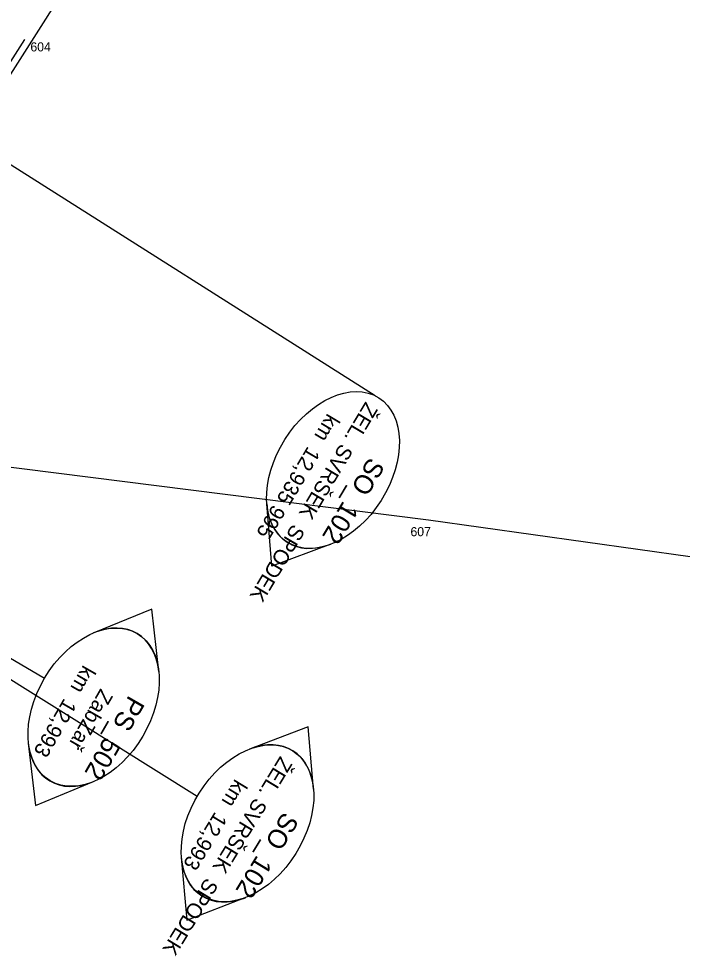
# Model space of a CAD drawing. Extents: x -743546 to -74, y -1128126 to -103.
# Drawn here: x -743132.9 to -743045.6, y -1127159.4 to -1127036 of the extents above; entities that cross this region are included whole.
import ezdxf

# ---------------------------------------------------------------- set-up
doc = ezdxf.new("R2010")
doc.units = 0
for name, color, linetype in [('_Násyp', 7, 'Continuous'), ('_TRASA_vedení kabelu_CEZ', 7, 'Continuous'), ('bublina_fialová_čára_tenká', 7, 'Continuous'), ('bublina_růžová_230_čára_tučná', 7, 'Continuous'), ('křížky', 7, 'Continuous'), ('Vrstva 53', 7, 'Continuous'), ('Vrstva 60', 7, 'Continuous')]:
    doc.layers.add(name, color=color, linetype=linetype)

# ---------------------------------------------------------------- blocks, each defined once
blk = doc.blocks.new('POINT_DISPLAY')
blk.add_line((0, 0), (0, 0))

msp = doc.modelspace()

# ---------------------------------------------------------------- linework, layer by layer
at = {"layer": '_TRASA_vedení kabelu_CEZ'}
for points in [[(-743153.07, -1127080.41), (-743148.26, -1127068.65), (-743137.26, -1127046.76), (-743132.07, -1127038.68)], [(-743154.26, -1127082.61), (-743159.25, -1127091.79), (-743078.98, -1127101.9), (-743017.04, -1127110.61), (-742993.93, -1127114.82), (-742964.82, -1127120.76), (-742937.74, -1127126.54), (-742940.65, -1127140.7), (-742943, -1127146.4)]]:
    msp.add_lwpolyline(points, dxfattribs=at)
at = {"layer": 'bublina_fialová_čára_tenká'}
for p, q in [((-743086, -1127085.59), (-743143.43, -1127049.19)), ((-743129.51, -1127122.8), (-743175.48, -1127095.85)), ((-743109.42, -1127138.31), (-743174.12, -1127097.81))]:
    msp.add_line(p, q, dxfattribs=at)
at = {"layer": 'bublina_růžová_230_čára_tučná'}
for p, q in [((-743099.58, -1127108.03), (-743100.27, -1127099.8)), ((-743099.58, -1127108.03), (-743100.27, -1127099.8)), ((-743091.85, -1127105.13), (-743099.58, -1127108.03)), ((-743091.85, -1127105.13), (-743099.58, -1127108.03)), ((-743115.4, -1127113.65), (-743123.03, -1127116.79)), ((-743115.4, -1127113.65), (-743123.03, -1127116.79)), ((-743114.46, -1127121.85), (-743115.4, -1127113.65)), ((-743114.46, -1127121.85), (-743115.4, -1127113.65)), ((-743094.84, -1127129.14), (-743102.55, -1127132.08)), ((-743094.84, -1127129.14), (-743102.55, -1127132.08)), ((-743094.11, -1127137.36), (-743094.84, -1127129.14)), ((-743094.11, -1127137.36), (-743094.84, -1127129.14)), ((-743131.63, -1127131.3), (-743130.69, -1127139.51)), ((-743131.63, -1127131.3), (-743130.69, -1127139.51)), ((-743130.69, -1127139.51), (-743123.06, -1127136.36)), ((-743130.69, -1127139.51), (-743123.06, -1127136.36)), ((-743111.53, -1127146.36), (-743110.8, -1127154.58)), ((-743111.53, -1127146.36), (-743110.8, -1127154.58)), ((-743110.8, -1127154.58), (-743103.09, -1127151.64)), ((-743110.8, -1127154.58), (-743103.09, -1127151.64))]:
    msp.add_line(p, q, dxfattribs=at)
for centre, major_axis in [((-743091.56, -1127095.35), (6.01, 9.51)), ((-743123.03, -1127126.57), (-5.72, -9.69)), ((-743102.8, -1127141.85), (-5.97, -9.53))]:
    msp.add_ellipse(centre, major_axis=major_axis, ratio=0.666667, dxfattribs=at)
for centre, major_axis in [((-743091.56, -1127095.35), (-6.02, -9.51)), ((-743123.03, -1127126.57), (5.72, 9.69)), ((-743102.8, -1127141.85), (5.97, 9.54)), ((-743123.07, -1127126.59), (-5.72, -9.69)), ((-743102.84, -1127141.87), (-5.97, -9.54))]:
    msp.add_ellipse(centre, major_axis=major_axis, ratio=0.666473, start_param=5.557317, end_param=7.009053, dxfattribs=at)
at = {"layer": 'Vrstva 53'}
msp.add_lwpolyline([(-743032.8, -1126884.17), (-743063.8, -1126932.98), (-743082.27, -1126962.07), (-743093.1, -1126978.92), (-743136.47, -1127047.12), (-743147.78, -1127068.8), (-743159.64, -1127094.74), (-743160.17, -1127095.91), (-743166.78, -1127095.57), (-743176.42, -1127093.47), (-743180.17, -1127093.19), (-743180.08, -1127092.14), (-743178.51, -1127091.81), (-743175.35, -1127091.16), (-743150.08, -1127051.72), (-743124.8, -1127012.28), (-743108.67, -1126985.4), (-743080.97, -1126930.41), (-743079.79, -1126928.05), (-743048.51, -1126865.51)], dxfattribs=at)
at = {"layer": 'Vrstva 60'}
for p, q in [((-743132.07, -1127038.68), (-743132.07, -1127038.68)), ((-743078.98, -1127101.9), (-743078.98, -1127101.9))]:
    msp.add_line(p, q, dxfattribs=at)

# ---------------------------------------------------------------- block references
at = {"layer": 'křížky', "xscale": 10, "yscale": 10, "rotation": 61.14491455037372}
for p in [(-743132.07, -1127038.68), (-743078.98, -1127101.9)]:
    msp.add_blockref('POINT_DISPLAY', p, dxfattribs=at)

# ---------------------------------------------------------------- texts
at = {"layer": '_Násyp'}
for s, height, rotation, p in [('ŽEL. SVRŠEK  SPODEK', 2, 239.1744, (-743087.27, -1127086.27)), ('km  12,935 995', 2, 239.1744, (-743092.27, -1127087.8)), ('SO_102', 2.5, 239.1744, (-743086.78, -1127093.56)), ('km  12,993', 2, 240.1217, (-743124.39, -1127120.92)), ('ZabZař', 2, 240.1217, (-743122.12, -1127124.02)), ('PS_502', 2.5, 240.1217, (-743118.38, -1127124.89)), ('ŽEL. SVRŠEK  SPODEK', 2, 238.6088, (-743098.49, -1127132.92)), ('km  12,993', 2, 238.6088, (-743104.43, -1127135.92)), ('SO_102', 2.5, 238.6088, (-743098.07, -1127140.22))]:
    msp.add_text(s, height=height, rotation=rotation, dxfattribs=at).set_placement(p)
at = {"layer": 'Vrstva 60'}
for s, p in [('604', (-743131.35, -1127040.26)), ('607', (-743081.37, -1127104.07))]:
    msp.add_text(s, height=1.2, dxfattribs=at).set_placement(p)

doc.saveas('drawing.dxf')
